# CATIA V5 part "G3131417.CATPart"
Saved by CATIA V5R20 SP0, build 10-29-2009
Part number: G3131417
Revision: 23
Definition: design
Nomenclature: G3131417
Source: made
Description: NOT SPECIFIED
Bounding box of the stored display mesh (mm): x -9 to 17, y -12.31 to 12.31, z -12.5 to 12.5
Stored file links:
  C:\Users\Raffaele\Desktop\3D X SITO CF\BOLEX\24-BUSH REF 313\G3131417.CATPart
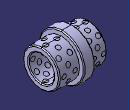
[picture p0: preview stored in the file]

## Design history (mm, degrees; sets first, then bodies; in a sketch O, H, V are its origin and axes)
Body1 "MANIFOLD_SOLID_BREP #6561" (main body)
  Solid1: solid without history
Body2 "MANIFOLD_SOLID_BREP #6704"
  Solid2: solid without history
Body3 "MANIFOLD_SOLID_BREP #6847"
  Solid3: solid without history
Body4 "MANIFOLD_SOLID_BREP #6990"
  Solid4: solid without history
Body5 "MANIFOLD_SOLID_BREP #7133"
  Solid5: solid without history
Body6 "MANIFOLD_SOLID_BREP #7276"
  Solid6: solid without history
Body7 "MANIFOLD_SOLID_BREP #7419"
  Solid7: solid without history
Body8 "MANIFOLD_SOLID_BREP #7564"
  Solid8: solid without history
Body9 "MANIFOLD_SOLID_BREP #7709"
  Solid9: solid without history
Body10 "MANIFOLD_SOLID_BREP #7854"
  Solid10: solid without history
Body11 "MANIFOLD_SOLID_BREP #7999"
  Solid11: solid without history
Body12 "MANIFOLD_SOLID_BREP #8142"
  Solid12: solid without history
Body13 "MANIFOLD_SOLID_BREP #8285"
  Solid13: solid without history
Body14 "MANIFOLD_SOLID_BREP #8430"
  Solid14: solid without history
Body15 "MANIFOLD_SOLID_BREP #8575"
  Solid15: solid without history
Body16 "MANIFOLD_SOLID_BREP #8720"
  Solid16: solid without history
Body17 "MANIFOLD_SOLID_BREP #8865"
  Solid17: solid without history
Body18 "MANIFOLD_SOLID_BREP #9010"
  Solid18: solid without history
Body19 "MANIFOLD_SOLID_BREP #9155"
  Solid19: solid without history
Body20 "MANIFOLD_SOLID_BREP #9300"
  Solid20: solid without history
Body21 "MANIFOLD_SOLID_BREP #9445"
  Solid21: solid without history
Body22 "MANIFOLD_SOLID_BREP #9590"
  Solid22: solid without history
Body23 "MANIFOLD_SOLID_BREP #9735"
  Solid23: solid without history
Body24 "MANIFOLD_SOLID_BREP #9880"
  Solid24: solid without history
Body25 "MANIFOLD_SOLID_BREP #10025"
  Solid25: solid without history
Body26 "MANIFOLD_SOLID_BREP #10168"
  Solid26: solid without history
Body27 "MANIFOLD_SOLID_BREP #10311"
  Solid27: solid without history
Body28 "MANIFOLD_SOLID_BREP #10456"
  Solid28: solid without history
Body29 "MANIFOLD_SOLID_BREP #10601"
  Solid29: solid without history
Body30 "MANIFOLD_SOLID_BREP #10746"
  Solid30: solid without history
Body31 "MANIFOLD_SOLID_BREP #10891"
  Solid31: solid without history
Body32 "MANIFOLD_SOLID_BREP #11034"
  Solid32: solid without history
Body33 "MANIFOLD_SOLID_BREP #11177"
  Solid33: solid without history
Body34 "MANIFOLD_SOLID_BREP #11322"
  Solid34: solid without history
Body35 "MANIFOLD_SOLID_BREP #11467"
  Solid35: solid without history
Body36 "MANIFOLD_SOLID_BREP #11612"
  Solid36: solid without history
Body37 "MANIFOLD_SOLID_BREP #11757"
  Solid37: solid without history
Body38 "MANIFOLD_SOLID_BREP #11900"
  Solid38: solid without history
Body39 "MANIFOLD_SOLID_BREP #12043"
  Solid39: solid without history
Body40 "MANIFOLD_SOLID_BREP #12186"
  Solid40: solid without history
Body41 "MANIFOLD_SOLID_BREP #12329"
  Solid41: solid without history
Body42 "MANIFOLD_SOLID_BREP #12474"
  Solid42: solid without history
Body43 "MANIFOLD_SOLID_BREP #12619"
  Solid43: solid without history
Body44 "MANIFOLD_SOLID_BREP #12764"
  Solid44: solid without history
Body45 "MANIFOLD_SOLID_BREP #12909"
  Solid45: solid without history
Body46 "MANIFOLD_SOLID_BREP #13054"
  Solid46: solid without history
Body47 "MANIFOLD_SOLID_BREP #13199"
  Solid47: solid without history
Body48 "MANIFOLD_SOLID_BREP #13344"
  Solid48: solid without history
Body49 "MANIFOLD_SOLID_BREP #13489"
  Solid49: solid without history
